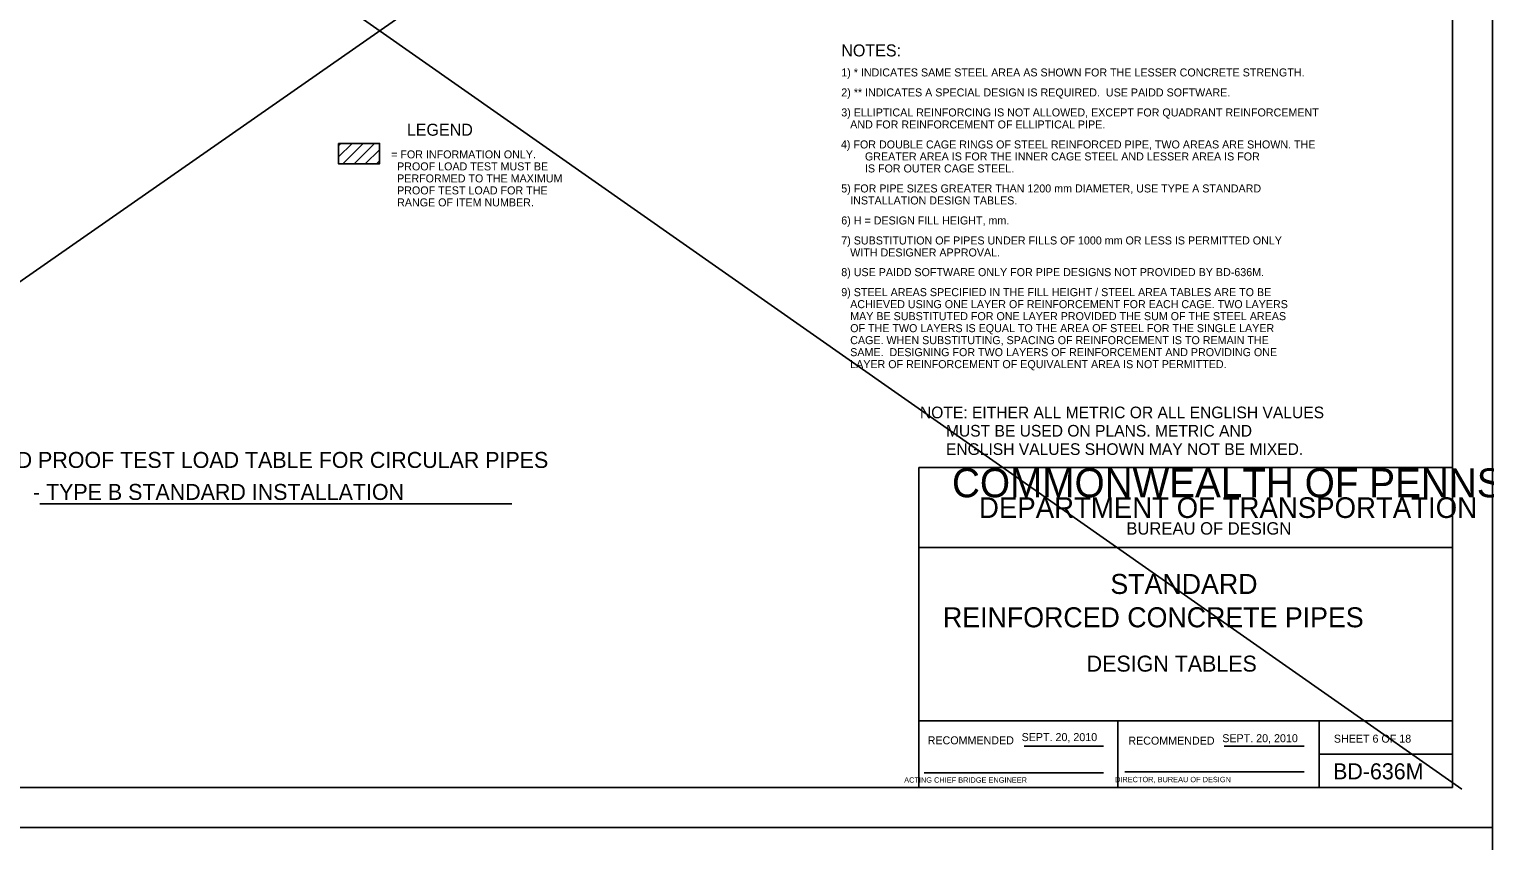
# Model space of a CAD drawing. Extents: x -22562 to -18409, y 3991 to 7171.
# Drawn here: x -20933 to -20388, y 6362 to 6667 of the extents above; entities that cross this region are included whole.
import ezdxf

# ---------------------------------------------------------------- set-up
doc = ezdxf.new("R2010")
doc.units = 0
for name, color, linetype in [('2', 7, 'Continuous'), ('Default', 7, 'Continuous'), ('PLT-BNDY', 7, 'Continuous')]:
    doc.layers.add(name, color=color, linetype=linetype)

msp = doc.modelspace()

# ---------------------------------------------------------------- linework, layer by layer
at = {"layer": '2'}
for p, q in [((-20399.85, 6946.37), (-20399.85, 6382.37)), ((-20817.45, 6623.05), (-20816.57, 6623.93)), ((-20817.45, 6618.93), (-20812.32, 6623.93)), ((-20815.82, 6616.3), (-20808.2, 6623.93)), ((-20811.57, 6616.3), (-20803.95, 6623.93)), ((-20807.45, 6616.3), (-20802.07, 6621.55)), ((-20803.2, 6616.3), (-20802.07, 6617.43)), ((-20399.85, 6502.37), (-20599.85, 6502.37)), ((-20599.85, 6502.37), (-20599.85, 6382.37)), ((-20399.85, 6382.37), (-20399.85, 6502.37)), ((-20929.35, 6488.74), (-20752.47, 6488.74)), ((-20399.85, 6472.37), (-20599.85, 6472.37)), ((-20399.85, 6407.37), (-20599.85, 6407.37)), ((-20525.35, 6382.37), (-20525.35, 6407.37)), ((-20449.85, 6407.37), (-20449.85, 6382.37)), ((-20560.38, 6397.87), (-20530.62, 6397.87)), ((-20485.38, 6397.87), (-20455.47, 6397.87)), ((-20449.85, 6394.87), (-20399.85, 6394.87)), ((-20597.85, 6387.87), (-20530.62, 6387.87)), ((-20522.72, 6388.24), (-20455.47, 6388.24)), ((-20399.85, 6382.37), (-21185.85, 6382.37)), ((-20599.85, 6382.37), (-20399.85, 6382.37))]:
    msp.add_line(p, q, dxfattribs=at)
msp.add_lwpolyline([(-20817.45, 6623.93), (-20802.07, 6623.93), (-20802.07, 6616.3), (-20817.45, 6616.3), (-20817.45, 6623.93)], dxfattribs=at)
at = {"layer": 'Default'}
for p, q in [((-21207.77, 6950.57), (-20396.3, 6381.8)), ((-21207.77, 6383.24), (-20396.3, 6949.13))]:
    msp.add_line(p, q, dxfattribs=at)
at = {"layer": 'PLT-BNDY'}
for points in [[(-21225.85, 6961.37), (-20384.85, 6961.37), (-20384.85, 6367.37), (-21225.85, 6367.37)], [(-21225.85, 6367.37), (-20384.85, 6367.37), (-20384.85, 5773.37), (-21225.85, 5773.37)]]:
    msp.add_lwpolyline(points, close=True, dxfattribs=at)

# ---------------------------------------------------------------- texts
at = {"layer": '2'}
for s, height, p in [('NOTES:', 4.5, (-20628.97, 6656.53)), ('1) * INDICATES SAME STEEL AREA AS SHOWN FOR THE LESSER CONCRETE STRENGTH.', 3, (-20628.97, 6649.03)), ('2) ** INDICATES A SPECIAL DESIGN IS REQUIRED.  USE PAIDD SOFTWARE.', 3, (-20628.97, 6641.53)), ('3) ELLIPTICAL REINFORCING IS NOT ALLOWED, EXCEPT FOR QUADRANT REINFORCEMENT', 3, (-20628.97, 6634.03)), ('LEGEND', 4.5, (-20791.82, 6626.8)), ('   AND FOR REINFORCEMENT OF ELLIPTICAL PIPE.', 3, (-20628.97, 6629.53)), ('4) FOR DOUBLE CAGE RINGS OF STEEL REINFORCED PIPE, TWO AREAS ARE SHOWN. THE', 3, (-20629.1, 6622.03)), ('= FOR INFORMATION ONLY.', 3, (-20797.7, 6618.3)), ('GREATER AREA IS FOR THE INNER CAGE STEEL AND LESSER AREA IS FOR', 3, (-20620.1, 6617.53)), ('  PROOF LOAD TEST MUST BE', 3, (-20797.7, 6613.8)), ('IS FOR OUTER CAGE STEEL.', 3, (-20620.1, 6613.03)), ('  PERFORMED TO THE MAXIMUM', 3, (-20797.7, 6609.3)), ('5) FOR PIPE SIZES GREATER THAN 1200 mm DIAMETER, USE TYPE A STANDARD', 3, (-20628.97, 6605.53)), ('  PROOF TEST LOAD FOR THE', 3, (-20797.7, 6604.8)), ('  RANGE OF ITEM NUMBER.', 3, (-20797.7, 6600.3)), ('   INSTALLATION DESIGN TABLES.', 3, (-20628.97, 6601.03)), ('6) H = DESIGN FILL HEIGHT, mm.', 3, (-20628.97, 6593.53)), ('7) SUBSTITUTION OF PIPES UNDER FILLS OF 1000 mm OR LESS IS PERMITTED ONLY', 3, (-20628.97, 6586.03)), ('   WITH DESIGNER APPROVAL.', 3, (-20628.97, 6581.53)), ('8) USE PAIDD SOFTWARE ONLY FOR PIPE DESIGNS NOT PROVIDED BY BD-636M.', 3, (-20628.97, 6574.15)), ('9) STEEL AREAS SPECIFIED IN THE FILL HEIGHT / STEEL AREA TABLES ARE TO BE', 3, (-20628.97, 6566.65)), ('   ACHIEVED USING ONE LAYER OF REINFORCEMENT FOR EACH CAGE. TWO LAYERS', 3, (-20628.97, 6562.15)), ('   MAY BE SUBSTITUTED FOR ONE LAYER PROVIDED THE SUM OF THE STEEL AREAS', 3, (-20628.97, 6557.65)), ('   OF THE TWO LAYERS IS EQUAL TO THE AREA OF STEEL FOR THE SINGLE LAYER', 3, (-20628.97, 6553.15)), ('   CAGE. WHEN SUBSTITUTING, SPACING OF REINFORCEMENT IS TO REMAIN THE', 3, (-20628.97, 6548.65)), ('   SAME.  DESIGNING FOR TWO LAYERS OF REINFORCEMENT AND PROVIDING ONE', 3, (-20628.97, 6544.15)), ('   LAYER OF REINFORCEMENT OF EQUIVALENT AREA IS NOT PERMITTED.', 3, (-20628.97, 6539.65)), ('NOTE: EITHER ALL METRIC OR ALL ENGLISH VALUES', 4.375, (-20599.49, 6520.86)), ('      MUST BE USED ON PLANS. METRIC AND', 4.375, (-20599.49, 6513.99)), ('      ENGLISH VALUES SHOWN MAY NOT BE MIXED.', 4.375, (-20599.49, 6507.11)), ('DESIGN TABLES AND PROOF TEST LOAD TABLE FOR CIRCULAR PIPES', 6, (-21015.22, 6502.24)), ('COMMONWEALTH OF PENNSYLVANIA', 10.8525, (-20587.47, 6491.24)), ('- TYPE B STANDARD INSTALLATION', 6, (-20931.97, 6490.24)), ('DEPARTMENT OF TRANSPORTATION', 7.7332, (-20577.35, 6483.49)), ('BUREAU OF DESIGN', 4.6493, (-20522.1, 6477.24)), ('STANDARD', 7.5, (-20528.1, 6454.99)), ('REINFORCED CONCRETE PIPES', 7.5, (-20590.85, 6442.49)), ('DESIGN TABLES', 6, (-20536.97, 6425.87)), ('SEPT. 20, 2010', 3, (-20561.37, 6399.82)), ('SEPT. 20, 2010', 3, (-20486.15, 6399.41)), ('SHEET 6 OF 18', 3, (-20444.32, 6399.24)), ('BD-636M', 6, (-20444.6, 6385.49)), ('       ACTING CHIEF BRIDGE ENGINEER', 2.0002, (-20610.76, 6384.24))]:
    msp.add_text(s, height=height, dxfattribs=at).set_placement(p)
for s, height, p in [('RECOMMENDED', 3, (-20596.58, 6398.62)), ('RECOMMENDED', 3, (-20521.36, 6398.49)), ('   DIRECTOR, BUREAU OF DESIGN', 2.0002, (-20528.65, 6384.42))]:
    msp.add_text(s, height=height, rotation=360, dxfattribs=at).set_placement(p)

doc.saveas('drawing.dxf')
